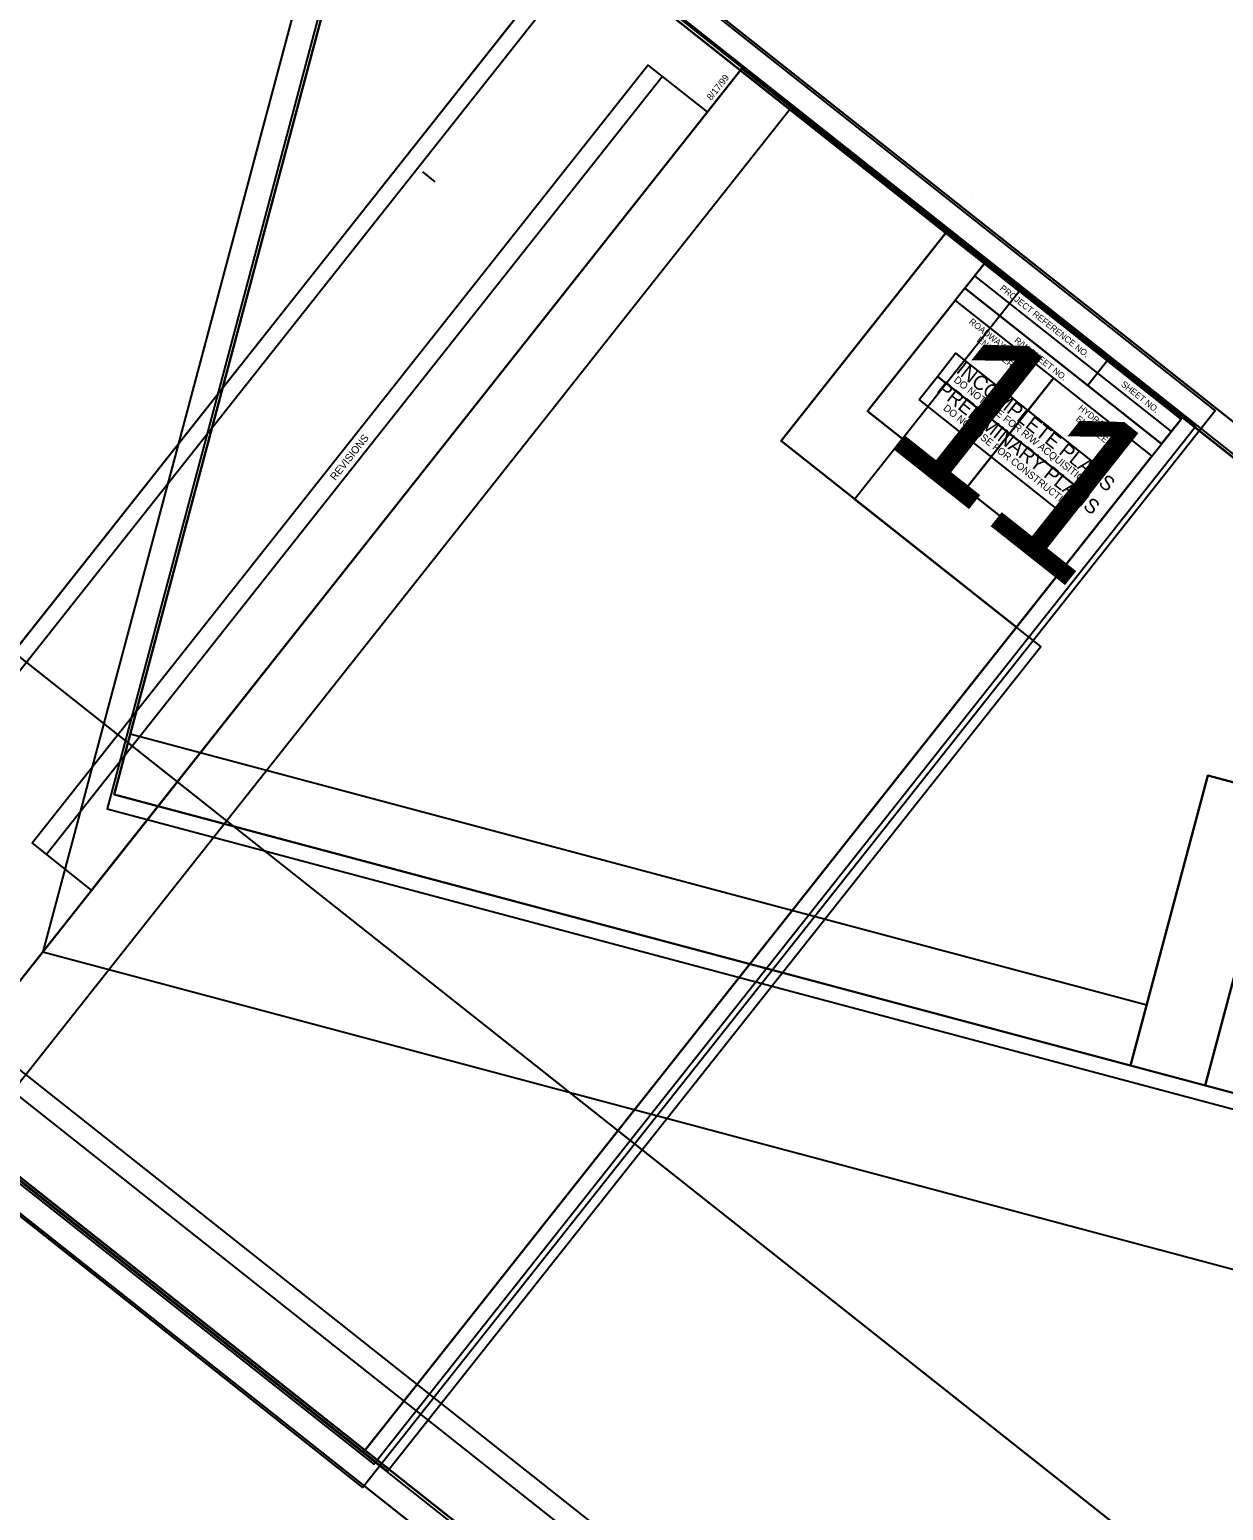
# Model space of a CAD drawing. Extents: x 1778994 to 1784559, y 810461 to 816654.
# Drawn here: x 1782142 to 1783094, y 813868 to 815048 of the extents above; entities that cross this region are included whole.
import ezdxf

# ---------------------------------------------------------------- set-up
doc = ezdxf.new("R2010")
doc.units = 0
for name, color, linetype in [('Sheet Block Revision CELL', 7, 'Continuous'), ('Sheet Clip Boundary CELL', 7, 'Continuous'), ('Sheet Cutting Line CELL', 7, 'Continuous'), ('Sheet Detail CELL', 7, 'Continuous'), ('Sheet Layout Plan Border', 7, 'Continuous'), ('Sheet North Arrow Point CELL', 7, 'Continuous'), ('Sheet Plan CELL', 7, 'Continuous'), ('Sheet Plan Layout CELL', 7, 'Continuous'), ('Sheet Plot Border Inside CELL', 7, 'Continuous'), ('Sheet Plot Border Outside CELL', 7, 'Continuous'), ('Sheet Sticker Incomplete CELL', 7, 'Continuous'), ('Sheet Sticker Preliminary CELL', 7, 'Continuous')]:
    doc.layers.add(name, color=color, linetype=linetype)

msp = doc.modelspace()

# ---------------------------------------------------------------- linework, layer by layer
at = {"layer": 'Sheet Block Revision CELL'}
msp.add_line((1782155.7, 814390.6), (1782646.5, 815010.5), dxfattribs=at)
msp.add_lwpolyline([(1782144.3, 814399.7), (1782635.1, 815019.5), (1782682.6, 814982), (1782191.8, 814362.1)], close=True, dxfattribs=at)
at = {"layer": 'Sheet Clip Boundary CELL'}
for points in [[(1782583.3, 815839.3), (1782222.6, 814486.6), (1783032.8, 814270.5), (1783081.5, 814453.4), (1783285.9, 814398.9), (1783597.9, 815568.8)], [(1781330.1, 814767.8), (1782427.7, 813898.8), (1782948.2, 814556.2), (1782799.8, 814673.7), (1782931.1, 814839.5), (1781981.8, 815591.1)], [(1782097.5, 814162.5), (1783195.2, 813293.5), (1783715.7, 813950.9), (1783567.3, 814068.4), (1783698.6, 814234.2), (1782749.3, 814985.7)], [(1780971.5, 813236.4), (1781770.7, 814245.9), (1782005.9, 814059.6), (1782091.3, 814167.4), (1783972.9, 812677.7), (1783879.8, 812560.1), (1784036.6, 812435.9), (1783245.2, 811436.3)]]:
    msp.add_lwpolyline(points, close=True, dxfattribs=at)
at = {"layer": 'Sheet Cutting Line CELL'}
for p, q in [((1782586.7, 815939.4), (1782152.9, 814312.8)), ((1783087.4, 814744.4), (1781767.5, 815789.4)), ((1782593.5, 815137.7), (1781913.8, 814279.2)), ((1783913.4, 814092.8), (1782593.5, 815137.7)), ((1781087.8, 814930.9), (1782407.7, 813885.9)), ((1784390.3, 812761.8), (1781749.7, 814852.4)), ((1781913.8, 814279.2), (1783233.7, 813234.2))]:
    msp.add_line(p, q, dxfattribs=at)
at = {"layer": 'Sheet Detail CELL'}
msp.add_lwpolyline([(1781847.9, 814423.9), (1784200, 812561.7), (1783175.8, 811268.1), (1780823.7, 813130.3)], close=True, dxfattribs=at)
at = {"layer": 'Sheet Layout Plan Border'}
for points in [[(1782583.3, 815839.3), (1782222.6, 814486.6), (1783032.8, 814270.5), (1783081.5, 814453.4), (1783285.9, 814398.9), (1783597.9, 815568.8)], [(1781330.1, 814767.8), (1782427.7, 813898.8), (1782948.2, 814556.2), (1782799.8, 814673.7), (1782931.1, 814839.5), (1781981.8, 815591.1)], [(1782097.5, 814162.5), (1783195.2, 813293.5), (1783715.7, 813950.9), (1783567.3, 814068.4), (1783698.6, 814234.2), (1782749.3, 814985.7)]]:
    msp.add_lwpolyline(points, close=True, dxfattribs=at)
at = {"layer": 'Sheet North Arrow Point CELL'}
msp.add_line((1782893.8, 814915.1), (1782893.8, 814915.1), dxfattribs=at)
at = {"layer": 'Sheet Plan CELL'}
for p, q in [((1782710.1, 815016.8), (1782710.1, 815016.8)), ((1782455.5, 814934.5), (1782465.4, 814926.7)), ((1782895.5, 814851.7), (1783052.3, 814727.5)), ((1782887.7, 814841.9), (1782880, 814832.1)), ((1782887.7, 814841.9), (1783044.6, 814717.7)), ((1782887.7, 814841.9), (1783044.6, 814717.7)), ((1783001.2, 814783.9), (1782985.8, 814764.3)), ((1782958.4, 814770), (1782888.6, 814681.8))]:
    msp.add_line(p, q, dxfattribs=at)
for points in [[(1783224.2, 814167.7), (1783610.8, 815617.1), (1782596.2, 815887.7), (1782209.7, 814438.3)], [(1782596.2, 815887.7), (1783610.7, 815617.1), (1783275.8, 814361), (1783130.8, 814399.7), (1783079.2, 814206.4), (1782209.7, 814438.3)], [(1783060.1, 814737.4), (1781884.1, 815668.5), (1781232.3, 814845.2), (1782408.4, 813914.1)], [(1781232.3, 814845.2), (1781884, 815668.5), (1782903.3, 814861.6), (1782810.1, 814743.9), (1782967, 814619.7), (1782408.4, 813914.1)], [(1783886.2, 814085.7), (1782710.1, 815016.8), (1782058.3, 814193.5), (1783234.4, 813262.4)], [(1782058.3, 814193.5), (1782710.1, 815016.8), (1783729.3, 814209.9), (1783636.2, 814092.2), (1783793, 813968), (1783234.4, 813262.4)], [(1782903.3, 814861.6), (1783060.1, 814737.4), (1783044.6, 814717.7), (1782887.7, 814841.9)], [(1782880, 814832.1), (1782958.4, 814770), (1782888.6, 814681.8), (1782810.1, 814743.9)], [(1782958.4, 814770), (1783036.8, 814707.9), (1782967, 814619.7), (1782888.6, 814681.8)], [(1783213.7, 814274), (1783188, 814177.4), (1783079.2, 814206.4), (1783105, 814303)]]:
    msp.add_lwpolyline(points, close=True, dxfattribs=at)
at = {"layer": 'Sheet Plan Layout CELL'}
for points in [[(1783610.7, 815617.1), (1782596.2, 815887.7), (1782209.7, 814438.3), (1783019.9, 814222.2), (1783081.5, 814453.4), (1783285.9, 814398.9)], [(1781884, 815668.5), (1781232.3, 814845.2), (1782408.3, 813914.1), (1782928.8, 814571.6), (1782741.3, 814720.1), (1782872.5, 814885.9)], [(1782710.1, 815016.8), (1782058.3, 814193.5), (1783234.4, 813262.4), (1783754.9, 813919.9), (1783567.3, 814068.4), (1783698.6, 814234.2)], [(1782741.3, 814720.1), (1782928.8, 814571.6), (1783060.1, 814737.3), (1782872.5, 814885.9)], [(1783081.5, 814453.4), (1783019.9, 814222.2), (1783224.2, 814167.7), (1783285.9, 814398.9)]]:
    msp.add_lwpolyline(points, close=True, dxfattribs=at)
at = {"layer": 'Sheet Plot Border Inside CELL'}
for points in [[(1782633.3, 816036.6), (1782204.1, 814426.9), (1783223.4, 814155), (1783652.7, 815764.7)], [(1781110.4, 814938.5), (1782416.6, 813904.4), (1783071.5, 814731.6), (1781765.3, 815765.7)], [(1781936.4, 814286.8), (1783242.6, 813252.7), (1783897.5, 814079.9), (1782591.3, 815114)], [(1784230.1, 812559.5), (1781642.9, 814607.9), (1780597.6, 813287.6), (1783184.8, 811239.2)]]:
    msp.add_lwpolyline(points, close=True, dxfattribs=at)
at = {"layer": 'Sheet Plot Border Outside CELL'}
for points in [[(1782586.7, 815939.4), (1782152.9, 814312.8), (1783210.9, 814030.6), (1783644.8, 815657.3)], [(1781087.8, 814930.9), (1782407.7, 813885.9), (1783087.4, 814744.4), (1781767.5, 815789.4)], [(1781913.8, 814279.2), (1783233.7, 813234.2), (1783913.4, 814092.8), (1782593.5, 815137.7)], [(1784390.3, 812761.8), (1781749.7, 814852.4), (1780384.1, 813127.6), (1783024.7, 811037)]]:
    msp.add_lwpolyline(points, close=True, dxfattribs=at)
at = {"layer": 'Sheet Sticker Incomplete CELL'}
msp.add_lwpolyline([(1782865.9, 814771.5), (1782880.4, 814789.9), (1782995.7, 814698.7), (1782981.1, 814680.3)], close=True, dxfattribs=at)
at = {"layer": 'Sheet Sticker Preliminary CELL'}
msp.add_lwpolyline([(1782851.3, 814753.1), (1782865.9, 814771.5), (1782981.1, 814680.3), (1782966.5, 814661.8)], close=True, dxfattribs=at)

# ---------------------------------------------------------------- texts
at = {"layer": 'Sheet Block Revision CELL'}
msp.add_text('REVISIONS', height=6, rotation=51.6309, dxfattribs=at).set_placement((1782386, 814688.1))
at = {"layer": 'Sheet Plan CELL'}
for s, height, rotation, p in [('8/17/99', 5.25, 51.6309, (1782685.7, 814991.2)), ('PROJECT REFERENCE NO.', 5, 321.6309, (1782915.3, 814840.9)), ('ROADWAY DESIGN', 5, 321.6309, (1782890.6, 814814.3)), ('ENGINEER', 5, 321.6309, (1782896.9, 814799.8)), ('R/W SHEET NO.', 5, 321.6309, (1782926.7, 814799.3)), ('SHEET NO.', 5, 321.6309, (1783011.8, 814764.4)), ('HYDRAULICS', 5, 321.6309, (1782977.8, 814745.4)), ('ENGINEER', 5, 321.6309, (1782975.8, 814736.8))]:
    msp.add_text(s, height=height, rotation=rotation, dxfattribs=at).set_placement(p)
at = {"layer": 'Sheet Plan Layout CELL'}
msp.add_text('11', height=131.25, rotation=321.6309, dxfattribs=at).set_placement((1782821.3, 814721))
at = {"layer": 'Sheet Sticker Incomplete CELL'}
for s, height, p in [('INCOMPLETE PLANS', 11.52, (1782880.1, 814775.1)), ('DO NOT USE FOR R/W ACQUISITION', 5.76, (1782878.4, 814767.7))]:
    msp.add_text(s, height=height, rotation=321.6309, dxfattribs=at).set_placement(p)
at = {"layer": 'Sheet Sticker Preliminary CELL'}
for s, height, p in [('PRELIMINARY PLANS', 11.52, (1782864.5, 814759.4)), ('DO NOT USE FOR CONSTRUCTION', 5.76, (1782870, 814745.2))]:
    msp.add_text(s, height=height, rotation=321.6309, dxfattribs=at).set_placement(p)

doc.saveas('drawing.dxf')
